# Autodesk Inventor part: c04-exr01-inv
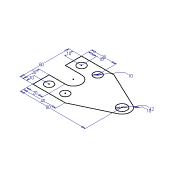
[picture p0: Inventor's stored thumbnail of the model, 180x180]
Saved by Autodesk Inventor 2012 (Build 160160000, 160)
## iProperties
Shininess: 64.0
Length Units: 11269
Angle Units: 11279
Time Units: 11290
Mass Units: 11283
Length Display Precision: 3
Angle Display Precision: 2
Compacted: True
Created: 2002-02
Part Number: c04-exr01-inv
Document SubType Name: Modeling
Density: 1 g/cm^3
Material: Default
Density: 0.0
Volumn: 0.0
Area: 0.0
PropertySet Name: Model Information
Control State: 0
Master: False
Checked Out: False
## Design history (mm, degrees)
sketch "Sketch1"
  geometry: L1 (-41.454, 11.298)-(-21.454, 11.298); L2 (-21.454, -8.702)-(-41.454, -8.702); L3 (-41.454, -8.702)-(-41.454, -28.702); L4 (-41.454, -28.702)-(-1.454, -28.702); L5 (-1.454, -28.702)-(42.825, -7.74); L6 (42.825, 10.337)-(-1.454, 31.298); L7 (-1.454, 31.298)-(-41.454, 31.298); L8 (-41.454, 31.298)-(-41.454, 11.298); C1 r 5 at (-31.454, 21.298); C2 r 5 at (-11.454, 21.298); C3 r 5 at (-31.454, -18.702); C4 r 5 at (-11.454, -18.702); C5 r 6 at (38.546, 1.298); A1 r 10 centre (-21.454, 1.298) between (-21.454, -8.702) and (-21.454, 11.298); A2 r 10 centre (38.546, 1.298) between (42.825, -7.74) and (42.825, 10.337)
  constraints: 16 end point, 7 centre point, 4 equal length, 4 point on circle, 4 tangent, 3 equal radius, 3 parallel, 2 vertical alignment, 1 coincident, 1 collinear, 1 horizontal, 1 horizontal alignment, 1 perpendicular
  dimensions: "d0" = 20 distance of L2.end L3.end; "d2" = 80 distance from line of A2.centre L3; "d3" = 10 radius of A2; "d4" = 40 distance of L3.end L4.end; "d5" = 20 distance of L2.start L2.end; "d6" = 60 distance between parallel lines of L4 L7; "d7" = 10 diameter of C2; "d8" = 10 distance from line of L8 C1.centre; "d9" = 30 distance from line of L8 C2.centre; "d10" = 10 distance from line of L7 C1.centre; "d11" = 10 distance from line of L4 C3.centre; "d12" = 12 diameter of C5
